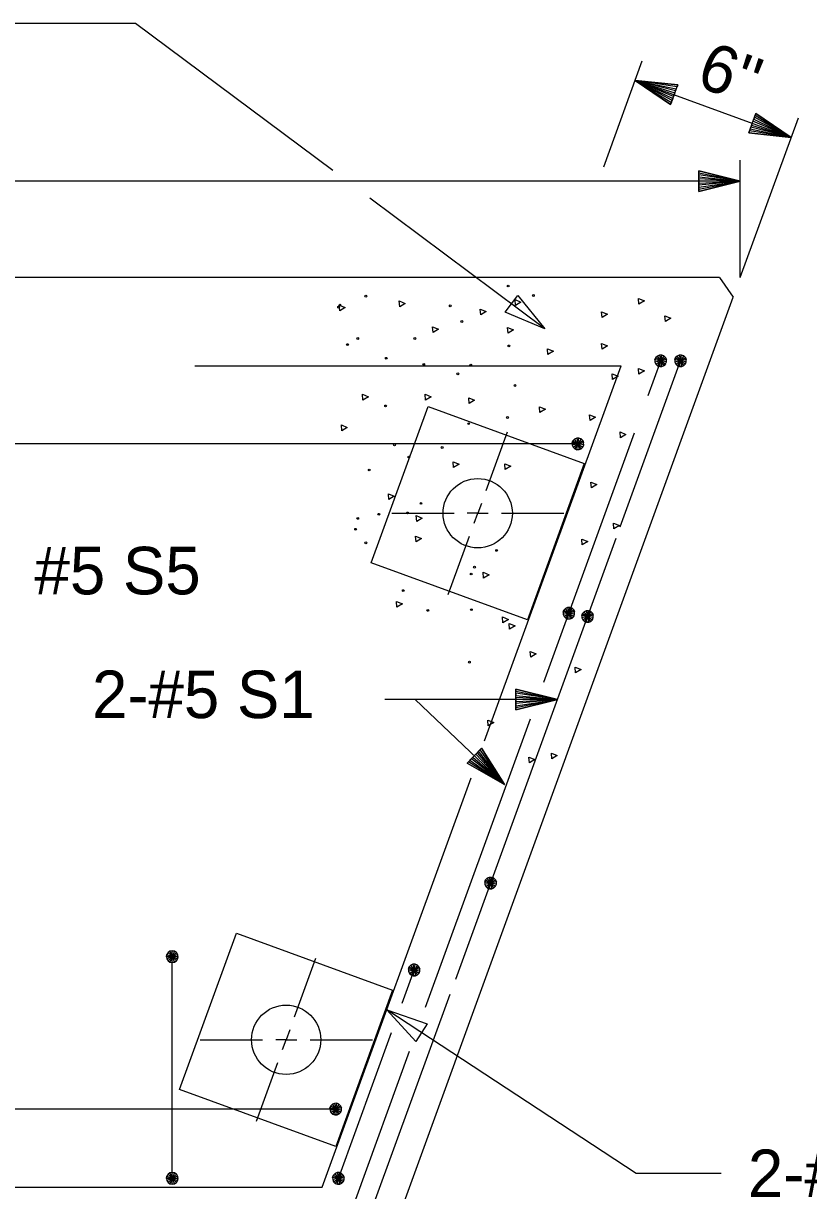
# Model space of a CAD drawing. Extents: x 0 to 177, y -1 to 130.
# Drawn here: x 170.484 to 172.847, y 69.344 to 72.854 of the extents above; entities that cross this region are included whole.
import ezdxf

# ---------------------------------------------------------------- set-up
doc = ezdxf.new("R2010")
doc.units = 0
for name, color, linetype in [('Arrowhead Terminators CELL', 7, 'Continuous'), ('Dimension Lines', 7, 'Continuous'), ('Rebar Lines', 7, 'Continuous'), ('Sup Concrete Girder Lines', 7, 'Continuous'), ('Sup Cored Slab Unit', 7, 'Continuous'), ('Text', 7, 'Continuous')]:
    doc.layers.add(name, color=color, linetype=linetype)

msp = doc.modelspace()

# ---------------------------------------------------------------- linework, layer by layer
at = {"layer": 'Arrowhead Terminators CELL'}
for points in [[(172.0529, 71.9358), (171.934, 71.9854), (171.9714, 72.0356)], [(171.5774, 69.8876), (171.699, 69.8452), (171.6648, 69.7929)]]:
    msp.add_lwpolyline(points, close=True, dxfattribs=at)
at = {"layer": 'Dimension Lines'}
for p, q in [((172.2302, 72.4229), (172.346, 72.741)), ((172.3246, 72.6822), (172.7945, 72.5112)), ((172.641, 72.0893), (172.8158, 72.57)), ((172.641, 72.0893), (172.641, 72.4423)), ((172.641, 72.3798), (168.849, 72.3798)), ((171.8763, 71.4498), (171.9404, 71.626)), ((171.5922, 71.3812), (171.7798, 71.3812)), ((171.9229, 71.3812), (172.1104, 71.3812)), ((171.7622, 71.1364), (171.8264, 71.3125)), ((172.0907, 70.8209), (171.6627, 70.8209)), ((171.2998, 69.8665), (171.364, 70.0426)), ((171.0158, 69.7979), (171.2033, 69.7979)), ((171.3465, 69.7979), (171.534, 69.7979)), ((171.1858, 69.5531), (171.2499, 69.7292))]:
    msp.add_line(p, q, dxfattribs=at)
for points in [[(171.4151, 72.4112), (170.8211, 72.854), (170.2621, 72.854)], [(172.4421, 72.6395), (172.4399, 72.6336), (172.3246, 72.6822), (172.4378, 72.6278), (172.4356, 72.6219), (172.3246, 72.6822), (172.4335, 72.616), (172.4314, 72.6101), (172.3246, 72.6822), (172.4527, 72.6688), (172.4506, 72.663), (172.3246, 72.6822), (172.4485, 72.6571), (172.4463, 72.6512), (172.3246, 72.6822), (172.4442, 72.6454), (172.4314, 72.6101), (172.4527, 72.6688), (172.3246, 72.6822), (172.4314, 72.6101)], [(172.6771, 72.554), (172.6749, 72.5481), (172.7945, 72.5112), (172.6727, 72.5423), (172.6706, 72.5364), (172.7945, 72.5112), (172.6685, 72.5305), (172.6663, 72.5246), (172.7945, 72.5112), (172.6877, 72.5834), (172.6856, 72.5775), (172.7945, 72.5112), (172.6834, 72.5717), (172.6813, 72.5657), (172.7945, 72.5112), (172.6791, 72.5598), (172.6663, 72.5246), (172.6877, 72.5834), (172.7945, 72.5112), (172.6663, 72.5246)], [(172.516, 72.3798), (172.516, 72.3735), (172.641, 72.3798), (172.516, 72.3673), (172.516, 72.361), (172.641, 72.3798), (172.516, 72.3548), (172.516, 72.3485), (172.641, 72.3798), (172.516, 72.411), (172.516, 72.4048), (172.641, 72.3798), (172.516, 72.3985), (172.516, 72.3923), (172.641, 72.3798), (172.516, 72.386), (172.516, 72.3485), (172.516, 72.411), (172.641, 72.3798), (172.516, 72.3485)], [(172.0529, 71.9358), (171.5265, 72.3282)], [(171.8622, 71.4106), (171.8513, 71.3812), (171.8829, 71.3811)], [(171.8403, 71.3515), (171.851, 71.381), (171.8196, 71.381)], [(171.9657, 70.8209), (171.9657, 70.8146), (172.0907, 70.8209), (171.9657, 70.8084), (171.9657, 70.8021), (172.0907, 70.8209), (171.9657, 70.7959), (171.9657, 70.7896), (172.0907, 70.8209), (171.9657, 70.8521), (171.9657, 70.8459), (172.0907, 70.8209), (171.9657, 70.8396), (171.9657, 70.8334), (172.0907, 70.8209), (171.9657, 70.8271), (171.9657, 70.7896), (171.9657, 70.8521), (172.0907, 70.8209), (171.9657, 70.7896)], [(171.9312, 70.5655), (171.6627, 70.8209), (171.5718, 70.8209)], [(171.8406, 70.6517), (171.8363, 70.6471), (171.9312, 70.5655), (171.832, 70.6426), (171.8277, 70.6381), (171.9312, 70.5655), (171.8234, 70.6336), (171.8191, 70.6291), (171.9312, 70.5655), (171.8622, 70.6743), (171.8578, 70.6698), (171.9312, 70.5655), (171.8535, 70.6653), (171.8492, 70.6607), (171.9312, 70.5655), (171.8449, 70.6562), (171.8191, 70.6291), (171.8622, 70.6743), (171.9312, 70.5655), (171.8191, 70.6291)], [(172.5832, 69.3961), (172.3272, 69.3961), (171.5774, 69.8876)], [(171.2857, 69.8273), (171.2749, 69.7979), (171.3065, 69.7977)], [(171.2639, 69.7682), (171.2746, 69.7976), (171.2432, 69.7977)]]:
    msp.add_lwpolyline(points, dxfattribs=at)
at = {"layer": 'Rebar Lines'}
for p, q in [((171, 71.8237), (172.2821, 71.8237)), ((171.8717, 70.6964), (172.2821, 71.8237)), ((172.2795, 71.3397), (172.4613, 71.8393)), ((172.3636, 71.735), (172.4015, 71.8393)), ((172.0497, 70.8727), (172.3226, 71.6226)), ((172.1525, 71.5893), (169.5058, 71.5893)), ((172.0876, 70.8124), (172.2672, 71.3059)), ((171.7848, 69.9803), (172.0876, 70.8124)), ((171.694, 69.8955), (172.0097, 70.7629)), ((171.3835, 69.3549), (171.8313, 70.5852)), ((170.9318, 69.3809), (170.9318, 70.0476)), ((171.6235, 69.9076), (171.6599, 70.0074)), ((171.5439, 69.3184), (171.768, 69.9346)), ((171.4318, 69.3809), (171.5913, 69.8191)), ((171.4841, 69.3184), (171.6461, 69.7636)), ((171.4239, 69.5893), (168.7364, 69.5893)), ((170.1014, 69.3549), (171.3835, 69.3549))]:
    msp.add_line(p, q, dxfattribs=at)
for points in [[(172.4189, 71.8362), (172.4187, 71.8431), (172.416, 71.8494), (172.411, 71.8542), (172.4046, 71.8567), (172.3977, 71.8565), (172.3914, 71.8537), (172.3867, 71.8488), (172.3842, 71.8423), (172.3843, 71.8355), (172.3871, 71.8292), (172.392, 71.8244), (172.3985, 71.8219), (172.4053, 71.8221), (172.4116, 71.8248), (172.4164, 71.8298), (172.4189, 71.8362), (172.4015, 71.8393), (172.3842, 71.8423), (172.3867, 71.8488), (172.4015, 71.8393), (172.3914, 71.8537), (172.3977, 71.8565), (172.4015, 71.8393), (172.4046, 71.8567), (172.411, 71.8542), (172.4015, 71.8393), (172.416, 71.8494), (172.4187, 71.8431), (172.4015, 71.8393), (172.4164, 71.8298), (172.4116, 71.8248), (172.4015, 71.8393), (172.4053, 71.8221), (172.3985, 71.8219), (172.4015, 71.8393), (172.392, 71.8244), (172.3871, 71.8292), (172.4015, 71.8393), (172.3843, 71.8355)], [(172.4786, 71.8363), (172.4785, 71.8431), (172.4758, 71.8494), (172.4708, 71.8542), (172.4643, 71.8567), (172.4575, 71.8566), (172.4512, 71.8537), (172.4464, 71.8488), (172.4439, 71.8424), (172.4441, 71.8356), (172.4468, 71.8293), (172.4518, 71.8245), (172.4582, 71.822), (172.4651, 71.8221), (172.4714, 71.8249), (172.4762, 71.8298), (172.4786, 71.8363), (172.4613, 71.8393), (172.4439, 71.8424), (172.4464, 71.8488), (172.4613, 71.8393), (172.4512, 71.8537), (172.4575, 71.8566), (172.4613, 71.8393), (172.4643, 71.8567), (172.4708, 71.8542), (172.4613, 71.8393), (172.4758, 71.8494), (172.4785, 71.8431), (172.4613, 71.8393), (172.4762, 71.8298), (172.4714, 71.8249), (172.4613, 71.8393), (172.4651, 71.8221), (172.4582, 71.822), (172.4613, 71.8393), (172.4518, 71.8245), (172.4468, 71.8293), (172.4613, 71.8393), (172.4441, 71.8356)], [(172.1698, 71.5862), (172.1697, 71.5931), (172.1669, 71.5994), (172.162, 71.6042), (172.1555, 71.6067), (172.1487, 71.6066), (172.1424, 71.6037), (172.1376, 71.5988), (172.1351, 71.5924), (172.1353, 71.5855), (172.1381, 71.5792), (172.1429, 71.5744), (172.1494, 71.5719), (172.1563, 71.5721), (172.1625, 71.5748), (172.1673, 71.5798), (172.1698, 71.5862), (172.1525, 71.5893), (172.1351, 71.5924), (172.1376, 71.5988), (172.1525, 71.5893), (172.1424, 71.6037), (172.1487, 71.6066), (172.1525, 71.5893), (172.1555, 71.6067), (172.162, 71.6042), (172.1525, 71.5893), (172.1669, 71.5994), (172.1697, 71.5931), (172.1525, 71.5893), (172.1673, 71.5798), (172.1625, 71.5748), (172.1525, 71.5893), (172.1563, 71.5721), (172.1494, 71.5719), (172.1525, 71.5893), (172.1429, 71.5744), (172.1381, 71.5792), (172.1525, 71.5893), (172.1353, 71.5855)], [(172.1426, 71.0772), (172.1425, 71.084), (172.1397, 71.0903), (172.1348, 71.0951), (172.1283, 71.0975), (172.1215, 71.0974), (172.1151, 71.0946), (172.1104, 71.0897), (172.1079, 71.0833), (172.1081, 71.0765), (172.1108, 71.0702), (172.1158, 71.0654), (172.1222, 71.0629), (172.1291, 71.063), (172.1353, 71.0658), (172.1401, 71.0707), (172.1426, 71.0772), (172.1252, 71.0803), (172.1079, 71.0833), (172.1104, 71.0897), (172.1252, 71.0803), (172.1151, 71.0946), (172.1215, 71.0974), (172.1252, 71.0803), (172.1283, 71.0975), (172.1348, 71.0951), (172.1252, 71.0803), (172.1397, 71.0903), (172.1425, 71.084), (172.1252, 71.0803), (172.1401, 71.0707), (172.1353, 71.0658), (172.1252, 71.0803), (172.1291, 71.063), (172.1222, 71.0629), (172.1252, 71.0803), (172.1158, 71.0654), (172.1108, 71.0702), (172.1252, 71.0803), (172.1081, 71.0765)], [(172.1987, 71.0673), (172.1986, 71.0741), (172.1959, 71.0804), (172.1909, 71.0852), (172.1845, 71.0877), (172.1776, 71.0875), (172.1713, 71.0847), (172.1666, 71.0798), (172.1641, 71.0734), (172.1642, 71.0666), (172.167, 71.0603), (172.1719, 71.0555), (172.1784, 71.053), (172.1852, 71.0531), (172.1915, 71.0559), (172.1963, 71.0608), (172.1987, 71.0673), (172.1814, 71.0703), (172.1641, 71.0734), (172.1666, 71.0798), (172.1814, 71.0703), (172.1713, 71.0847), (172.1776, 71.0875), (172.1814, 71.0703), (172.1845, 71.0877), (172.1909, 71.0852), (172.1814, 71.0703), (172.1959, 71.0804), (172.1986, 71.0741), (172.1814, 71.0703), (172.1963, 71.0608), (172.1915, 71.0559), (172.1814, 71.0703), (172.1852, 71.0531), (172.1784, 71.053), (172.1814, 71.0703), (172.1719, 71.0555), (172.167, 71.0603), (172.1814, 71.0703), (172.1642, 71.0666)], [(171.9071, 70.2657), (171.907, 70.2725), (171.9042, 70.2788), (171.8992, 70.2836), (171.8928, 70.2861), (171.8859, 70.286), (171.8796, 70.2832), (171.8749, 70.2782), (171.8724, 70.2718), (171.8725, 70.2649), (171.8753, 70.2586), (171.8802, 70.2538), (171.8866, 70.2513), (171.8936, 70.2515), (171.8998, 70.2543), (171.9046, 70.2593), (171.9071, 70.2657), (171.8897, 70.2687), (171.8724, 70.2718), (171.8749, 70.2782), (171.8897, 70.2687), (171.8796, 70.2832), (171.8859, 70.286), (171.8897, 70.2687), (171.8928, 70.2861), (171.8992, 70.2836), (171.8897, 70.2687), (171.9042, 70.2788), (171.907, 70.2725), (171.8897, 70.2687), (171.9046, 70.2593), (171.8998, 70.2543), (171.8897, 70.2687), (171.8936, 70.2515), (171.8866, 70.2513), (171.8897, 70.2687), (171.8802, 70.2538), (171.8753, 70.2586), (171.8897, 70.2687), (171.8725, 70.2649)], [(170.9495, 70.0476), (170.9481, 70.0543), (170.9443, 70.06), (170.9386, 70.0639), (170.9318, 70.0652), (170.9251, 70.0639), (170.9194, 70.06), (170.9156, 70.0544), (170.9142, 70.0476), (170.9156, 70.0409), (170.9194, 70.0352), (170.9251, 70.0313), (170.9318, 70.0299), (170.9386, 70.0313), (170.9443, 70.0351), (170.9481, 70.0408), (170.9495, 70.0476), (170.9318, 70.0476), (170.9142, 70.0476), (170.9156, 70.0544), (170.9318, 70.0476), (170.9194, 70.06), (170.9251, 70.0639), (170.9318, 70.0476), (170.9318, 70.0652), (170.9386, 70.0639), (170.9318, 70.0476), (170.9443, 70.06), (170.9481, 70.0543), (170.9318, 70.0476), (170.9481, 70.0408), (170.9443, 70.0351), (170.9318, 70.0476), (170.9386, 70.0313), (170.9318, 70.0299), (170.9318, 70.0476), (170.9251, 70.0313), (170.9194, 70.0352), (170.9318, 70.0476), (170.9156, 70.0409)], [(171.6772, 70.0043), (171.6771, 70.0112), (171.6743, 70.0175), (171.6694, 70.0223), (171.6629, 70.0247), (171.6561, 70.0246), (171.6497, 70.0218), (171.645, 70.0169), (171.6425, 70.0104), (171.6427, 70.0036), (171.6454, 69.9973), (171.6504, 69.9925), (171.6568, 69.99), (171.6637, 69.9902), (171.67, 69.9929), (171.6747, 69.9979), (171.6772, 70.0043), (171.6599, 70.0074), (171.6425, 70.0104), (171.645, 70.0169), (171.6599, 70.0074), (171.6497, 70.0218), (171.6561, 70.0246), (171.6599, 70.0074), (171.6629, 70.0247), (171.6694, 70.0223), (171.6599, 70.0074), (171.6743, 70.0175), (171.6771, 70.0112), (171.6599, 70.0074), (171.6747, 69.9979), (171.67, 69.9929), (171.6599, 70.0074), (171.6637, 69.9902), (171.6568, 69.99), (171.6599, 70.0074), (171.6504, 69.9925), (171.6454, 69.9973), (171.6599, 70.0074), (171.6427, 70.0036)], [(171.4412, 69.5862), (171.4411, 69.5931), (171.4383, 69.5994), (171.4333, 69.6042), (171.4269, 69.6067), (171.4201, 69.6066), (171.4138, 69.6037), (171.409, 69.5988), (171.4065, 69.5924), (171.4067, 69.5855), (171.4094, 69.5792), (171.4143, 69.5744), (171.4208, 69.5719), (171.4277, 69.5721), (171.4339, 69.5748), (171.4387, 69.5798), (171.4412, 69.5862), (171.4239, 69.5893), (171.4065, 69.5924), (171.409, 69.5988), (171.4239, 69.5893), (171.4138, 69.6037), (171.4201, 69.6066), (171.4239, 69.5893), (171.4269, 69.6067), (171.4333, 69.6042), (171.4239, 69.5893), (171.4383, 69.5994), (171.4411, 69.5931), (171.4239, 69.5893), (171.4387, 69.5798), (171.4339, 69.5748), (171.4239, 69.5893), (171.4277, 69.5721), (171.4208, 69.5719), (171.4239, 69.5893), (171.4143, 69.5744), (171.4094, 69.5792), (171.4239, 69.5893), (171.4067, 69.5855)], [(170.9495, 69.3809), (170.9481, 69.3877), (170.9443, 69.3934), (170.9386, 69.3972), (170.9318, 69.3985), (170.9251, 69.3972), (170.9194, 69.3934), (170.9156, 69.3877), (170.9142, 69.3809), (170.9156, 69.3742), (170.9194, 69.3685), (170.9251, 69.3646), (170.9318, 69.3633), (170.9386, 69.3646), (170.9443, 69.3684), (170.9481, 69.3742), (170.9495, 69.3809), (170.9318, 69.3809), (170.9142, 69.3809), (170.9156, 69.3877), (170.9318, 69.3809), (170.9194, 69.3934), (170.9251, 69.3972), (170.9318, 69.3809), (170.9318, 69.3985), (170.9386, 69.3972), (170.9318, 69.3809), (170.9443, 69.3934), (170.9481, 69.3877), (170.9318, 69.3809), (170.9481, 69.3742), (170.9443, 69.3684), (170.9318, 69.3809), (170.9386, 69.3646), (170.9318, 69.3633), (170.9318, 69.3809), (170.9251, 69.3646), (170.9194, 69.3685), (170.9318, 69.3809), (170.9156, 69.3742)], [(171.4492, 69.3779), (171.4491, 69.3847), (171.4463, 69.391), (171.4414, 69.3958), (171.4349, 69.3983), (171.4281, 69.3982), (171.4217, 69.3954), (171.4171, 69.3904), (171.4145, 69.384), (171.4147, 69.3771), (171.4174, 69.3708), (171.4224, 69.366), (171.4288, 69.3635), (171.4357, 69.3637), (171.442, 69.3665), (171.4467, 69.3715), (171.4492, 69.3779), (171.4318, 69.3809), (171.4145, 69.384), (171.4171, 69.3904), (171.4318, 69.3809), (171.4217, 69.3954), (171.4281, 69.3982), (171.4318, 69.3809), (171.4349, 69.3983), (171.4414, 69.3958), (171.4318, 69.3809), (171.4463, 69.391), (171.4491, 69.3847), (171.4318, 69.3809), (171.4467, 69.3715), (171.442, 69.3665), (171.4318, 69.3809), (171.4357, 69.3637), (171.4288, 69.3635), (171.4318, 69.3809), (171.4224, 69.366), (171.4174, 69.3708), (171.4318, 69.3809), (171.4147, 69.3771)]]:
    msp.add_lwpolyline(points, dxfattribs=at)
at = {"layer": 'Sup Concrete Girder Lines'}
for p, q in [((172.5785, 72.0893), (167.0228, 72.0893)), ((172.5785, 72.0893), (172.6196, 72.0306)), ((171.549, 69.0893), (172.6196, 72.0306))]:
    msp.add_line(p, q, dxfattribs=at)
for points in [[(172.3362, 72.0093), (172.3347, 72.0265), (172.3527, 72.0194), (172.3362, 72.0093)], [(171.436, 71.9897), (171.4346, 72.0069), (171.4525, 71.9998), (171.436, 71.9897)], [(171.6163, 72.002), (171.6149, 72.0192), (171.6328, 72.0121), (171.6163, 72.002)], [(171.8602, 71.9773), (171.8587, 71.9946), (171.8767, 71.9874), (171.8602, 71.9773)], [(171.9647, 72.006), (171.9632, 72.0233), (171.9812, 72.0161), (171.9647, 72.006)], [(172.2249, 71.9695), (172.2235, 71.9868), (172.2414, 71.9796), (172.2249, 71.9695)], [(172.4156, 71.9577), (172.4142, 71.9749), (172.4322, 71.9678), (172.4156, 71.9577)], [(171.7167, 71.9241), (171.7153, 71.9413), (171.7333, 71.9342), (171.7167, 71.9241)], [(171.9421, 71.922), (171.9406, 71.9393), (171.9586, 71.9321), (171.9421, 71.922)], [(172.2249, 71.8742), (172.2235, 71.8915), (172.2414, 71.8843), (172.2249, 71.8742)], [(172.062, 71.8583), (172.0605, 71.8755), (172.0785, 71.8684), (172.062, 71.8583)], [(172.3362, 71.7987), (172.3347, 71.8159), (172.3527, 71.8088), (172.3362, 71.7987)], [(172.2567, 71.7828), (172.2552, 71.8), (172.2732, 71.7929), (172.2567, 71.7828)], [(171.5057, 71.7212), (171.5042, 71.7385), (171.5222, 71.7313), (171.5057, 71.7212)], [(171.6942, 71.7212), (171.6927, 71.7385), (171.7107, 71.7313), (171.6942, 71.7212)], [(171.8253, 71.711), (171.8239, 71.7282), (171.8418, 71.7211), (171.8253, 71.711)], [(172.0382, 71.6835), (172.0367, 71.7007), (172.0547, 71.6936), (172.0382, 71.6835)], [(172.1891, 71.6596), (172.1877, 71.6769), (172.2056, 71.6697), (172.1891, 71.6596)], [(171.4422, 71.6291), (171.4407, 71.6463), (171.4587, 71.6392), (171.4422, 71.6291)], [(172.2805, 71.608), (172.2791, 71.6253), (172.2971, 71.6181), (172.2805, 71.608)], [(171.7782, 71.5184), (171.7767, 71.5356), (171.7947, 71.5285), (171.7782, 71.5184)], [(171.9339, 71.5122), (171.9325, 71.5295), (171.9504, 71.5223), (171.9339, 71.5122)], [(172.1931, 71.457), (172.1917, 71.4743), (172.2097, 71.4671), (172.1931, 71.457)], [(171.5836, 71.4221), (171.5821, 71.4393), (171.6001, 71.4322), (171.5836, 71.4221)], [(171.6676, 71.3565), (171.6661, 71.3737), (171.6841, 71.3666), (171.6676, 71.3565)], [(172.2607, 71.3338), (172.2592, 71.3511), (172.2772, 71.344), (172.2607, 71.3338)], [(171.6655, 71.295), (171.664, 71.3123), (171.682, 71.3052), (171.6655, 71.295)], [(172.1653, 71.2862), (172.1639, 71.3034), (172.1818, 71.2963), (172.1653, 71.2862)], [(171.8688, 71.186), (171.8673, 71.2033), (171.8853, 71.1961), (171.8688, 71.186)], [(171.6081, 71.0984), (171.6067, 71.1156), (171.6247, 71.1085), (171.6081, 71.0984)], [(171.927, 71.0518), (171.9255, 71.069), (171.9435, 71.0619), (171.927, 71.0518)], [(171.9468, 71.0319), (171.9453, 71.0491), (171.9633, 71.042), (171.9468, 71.0319)], [(172.0104, 70.9484), (172.0089, 70.9657), (172.0269, 70.9585), (172.0104, 70.9484)], [(172.1454, 70.9008), (172.144, 70.918), (172.162, 70.9109), (172.1454, 70.9008)], [(171.8825, 70.7417), (171.8811, 70.759), (171.899, 70.7518), (171.8825, 70.7417)], [(172.0739, 70.6425), (172.0725, 70.6598), (172.0904, 70.6527), (172.0739, 70.6425)], [(172.0064, 70.6306), (172.0049, 70.6479), (172.0229, 70.6407), (172.0064, 70.6306)]]:
    msp.add_lwpolyline(points, dxfattribs=at)
for centre, radius in [((171.9427, 72.0642), 0.00273), ((171.5145, 72.0335), 0.00273), ((172.0185, 72.0356), 0.00273), ((171.4325, 72.0007), 0.00273), ((171.4366, 72.0069), 0.00273), ((171.7685, 72.0048), 0.00273), ((171.8034, 71.9577), 0.00273), ((171.4591, 71.888), 0.00273), ((171.4899, 71.9064), 0.00273), ((171.662, 71.9064), 0.00273), ((171.9447, 71.8839), 0.00273), ((171.5759, 71.847), 0.00273), ((171.6886, 71.8286), 0.00273), ((171.83, 71.8265), 0.00273), ((171.7911, 71.7999), 0.00273), ((171.9631, 71.7651), 0.00273), ((171.5739, 71.7036), 0.00273), ((171.8238, 71.6503), 0.00273), ((171.9406, 71.6688), 0.00273), ((171.6005, 71.5868), 0.00273), ((171.7439, 71.5786), 0.00273), ((171.6435, 71.5499), 0.00273), ((171.5247, 71.511), 0.00273), ((171.851, 71.381), 0.1042), ((171.6804, 71.4106), 0.00273), ((171.4899, 71.3655), 0.00273), ((171.5534, 71.3778), 0.00273), ((171.6394, 71.3819), 0.00273), ((171.4837, 71.3327), 0.00273), ((171.5145, 71.2918), 0.00273), ((171.9078, 71.2692), 0.00273), ((171.8415, 71.2187), 0.00273), ((171.8312, 71.1982), 0.00273), ((171.6271, 71.1483), 0.00273), ((171.7009, 71.0889), 0.00273), ((171.832, 71.091), 0.00273), ((171.8259, 70.9332), 0.00273), ((171.2746, 69.7977), 0.1042)]:
    msp.add_circle(centre, radius, dxfattribs=at)
at = {"layer": 'Sup Cored Slab Unit'}
for points in [[(171.7016, 71.7014), (172.1714, 71.5304), (172.0004, 71.0606), (171.5306, 71.2316)], [(171.1252, 70.1181), (171.595, 69.9471), (171.424, 69.4772), (170.9541, 69.6482)]]:
    msp.add_lwpolyline(points, close=True, dxfattribs=at)

# ---------------------------------------------------------------- texts
at = {"layer": 'Text'}
msp.add_text("6''", height=0.14302, rotation=340.0105, dxfattribs=at).set_placement((172.5032, 72.6674))
for s, p in [('#5 S5', (170.5177, 71.137)), ('2-#5 S1', (170.6906, 70.7649)), ('2-#4 S4', (172.664, 69.3246))]:
    msp.add_text(s, height=0.14302, dxfattribs=at).set_placement(p)

doc.saveas('drawing.dxf')
